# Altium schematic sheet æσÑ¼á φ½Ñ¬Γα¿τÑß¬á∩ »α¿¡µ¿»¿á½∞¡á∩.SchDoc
size A4
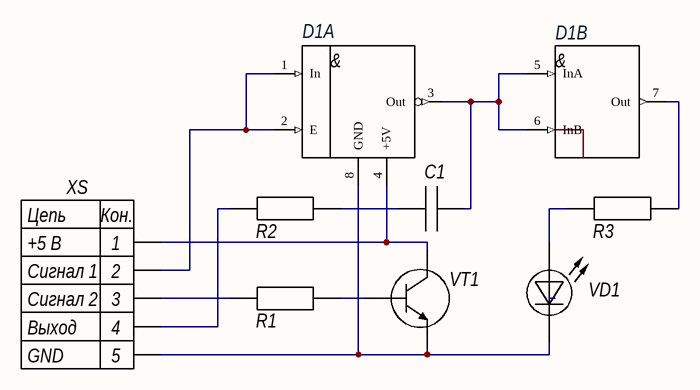
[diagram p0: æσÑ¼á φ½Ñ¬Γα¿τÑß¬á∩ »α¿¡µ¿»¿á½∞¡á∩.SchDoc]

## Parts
?  Соединитель  [для соединителя]  (value not drawn)
D1  Микросхема  [DIP8]  (value not drawn)  (parts A,B of 2)
R1  резистор  [ПМ для резистора]  (value not drawn)
R2  резистор  [ПМ для резистора]  (value not drawn)
R3  резистор  [ПМ для резистора]  (value not drawn)
VD1  Светодиод  [для светоиода]  (value not drawn)
VT1  КТ315  [ПМ для кт 315]  (value not drawn)
С1  Конденсатор  [для электролитич.конденсатора]  (value not drawn)

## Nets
Net?_1: ?.1 D1.4(+5V) VT1.C
Net?_2: ?.2 D1.1(In) D1.2(E)
Net?_3: ?.3 R1.2
Net?_4: ?.4 R2.2
Net?_5: ?.5 D1.8(GND) VD1.K VT1.E
NetD1_3: D1.3(Out) D1.5(InA) D1.6(InB) С1.2
NetD1_7: D1.7(Out) R3.1
NetR1_1: R1.1 VT1.B
NetR2_1: R2.1 С1.1
NetR3_2: R3.2 VD1.A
